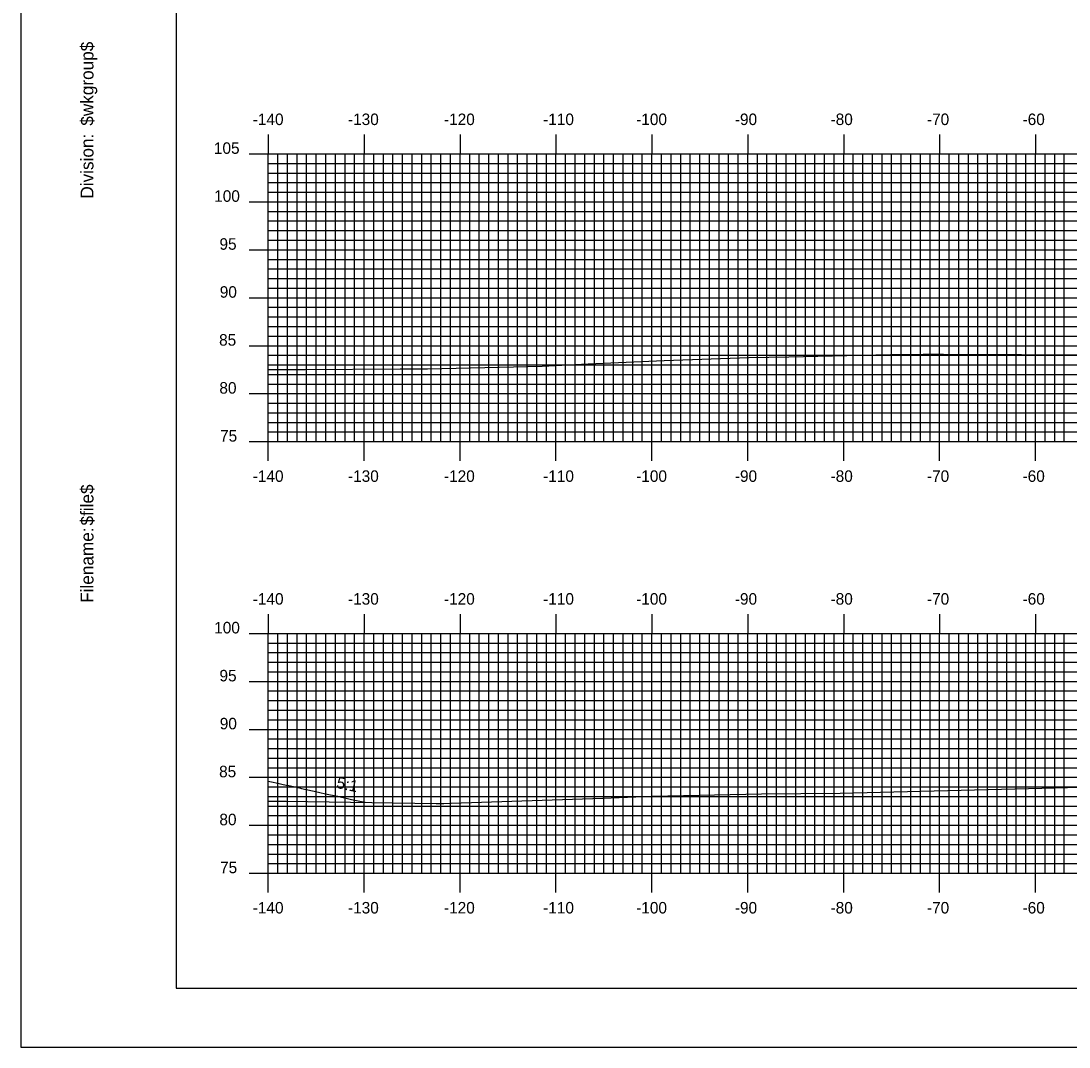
# Model space of a CAD drawing. Extents: x 2059 to 2403, y -1658 to -1438.
# Drawn here: x 2059.4 to 2168.7, y -1657.7 to -1550.7 of the extents above; entities that cross this region are included whole.
import ezdxf

# ---------------------------------------------------------------- set-up
doc = ezdxf.new("R2010")
doc.units = 0
for name, color, linetype in [('ANNOTATION', 7, 'Continuous'), ('BORDER', 7, 'Continuous'), ('D_Roadway_Centerline', 7, 'Continuous'), ('H_V ANNOTATION', 7, 'Continuous'), ('MAJOR', 7, 'Continuous'), ('MINOR', 7, 'Continuous'), ('PLOT BOUNDARY', 7, 'Continuous'), ('S_Roadway_Centerline', 7, 'Continuous')]:
    doc.layers.add(name, color=color, linetype=linetype)

msp = doc.modelspace()

# ---------------------------------------------------------------- linework, layer by layer
at = {"layer": 'BORDER'}
msp.add_lwpolyline([(2075.59, -1651.6), (2395.59, -1651.6), (2395.59, -1441.6), (2075.59, -1441.6)], close=True, dxfattribs=at)
at = {"layer": 'D_Roadway_Centerline'}
msp.add_lwpolyline([(2085.19, -1630), (2085.71, -1630.11), (2086.01, -1630.18), (2087.07, -1630.41), (2087.33, -1630.47), (2088.44, -1630.71), (2088.65, -1630.76), (2089.8, -1631.01), (2089.97, -1631.05), (2091.16, -1631.31), (2092.42, -1631.58), (2092.52, -1631.6), (2093.13, -1631.74), (2093.16, -1631.74), (2093.85, -1631.9), (2093.88, -1631.9), (2095.24, -1632.2), (2095.24, -1632.2), (2095.3, -1632.21)], dxfattribs=at)
at = {"layer": 'MAJOR'}
for p, q in [((2085.19, -1562.6), (2085.19, -1564.6)), ((2095.19, -1562.6), (2095.19, -1564.6)), ((2105.19, -1562.6), (2105.19, -1564.6)), ((2115.19, -1562.6), (2115.19, -1564.6)), ((2125.19, -1562.6), (2125.19, -1564.6)), ((2135.19, -1562.6), (2135.19, -1564.6)), ((2145.19, -1562.6), (2145.19, -1564.6)), ((2155.19, -1562.6), (2155.19, -1564.6)), ((2165.19, -1562.6), (2165.19, -1564.6)), ((2083.18, -1564.6), (2085.19, -1564.6)), ((2085.19, -1564.6), (2365.19, -1564.6)), ((2085.19, -1594.6), (2085.19, -1564.6)), ((2085.19, -1594.6), (2085.19, -1564.6)), ((2085.19, -1564.6), (2365.19, -1564.6)), ((2095.19, -1594.6), (2095.19, -1564.6)), ((2105.19, -1594.6), (2105.19, -1564.6)), ((2115.19, -1594.6), (2115.19, -1564.6)), ((2125.19, -1594.6), (2125.19, -1564.6)), ((2135.19, -1594.6), (2135.19, -1564.6)), ((2145.19, -1594.6), (2145.19, -1564.6)), ((2155.19, -1594.6), (2155.19, -1564.6)), ((2165.19, -1594.6), (2165.19, -1564.6)), ((2083.18, -1569.6), (2085.19, -1569.6)), ((2085.19, -1569.6), (2365.19, -1569.6)), ((2083.18, -1574.6), (2085.19, -1574.6)), ((2085.19, -1574.6), (2365.19, -1574.6)), ((2083.18, -1579.6), (2085.19, -1579.6)), ((2085.19, -1579.6), (2365.19, -1579.6)), ((2083.18, -1584.6), (2085.19, -1584.6)), ((2085.19, -1584.6), (2365.19, -1584.6)), ((2083.18, -1589.6), (2085.19, -1589.6)), ((2085.19, -1589.6), (2365.19, -1589.6)), ((2083.18, -1594.6), (2085.19, -1594.6)), ((2085.19, -1594.6), (2365.19, -1594.6)), ((2085.19, -1594.6), (2365.19, -1594.6)), ((2085.19, -1596.61), (2085.19, -1594.6)), ((2095.19, -1596.61), (2095.19, -1594.6)), ((2105.19, -1596.61), (2105.19, -1594.6)), ((2115.19, -1596.61), (2115.19, -1594.6)), ((2125.19, -1596.61), (2125.19, -1594.6)), ((2135.19, -1596.61), (2135.19, -1594.6)), ((2145.19, -1596.61), (2145.19, -1594.6)), ((2155.19, -1596.61), (2155.19, -1594.6)), ((2165.19, -1596.61), (2165.19, -1594.6)), ((2085.19, -1612.6), (2085.19, -1614.6)), ((2095.19, -1612.6), (2095.19, -1614.6)), ((2105.19, -1612.6), (2105.19, -1614.6)), ((2115.19, -1612.6), (2115.19, -1614.6)), ((2125.19, -1612.6), (2125.19, -1614.6)), ((2135.19, -1612.6), (2135.19, -1614.6)), ((2145.19, -1612.6), (2145.19, -1614.6)), ((2155.19, -1612.6), (2155.19, -1614.6)), ((2165.19, -1612.6), (2165.19, -1614.6)), ((2083.18, -1614.6), (2085.19, -1614.6)), ((2085.19, -1614.6), (2365.19, -1614.6)), ((2085.19, -1639.6), (2085.19, -1614.6)), ((2085.19, -1639.6), (2085.19, -1614.6)), ((2085.19, -1614.6), (2365.19, -1614.6)), ((2095.19, -1639.6), (2095.19, -1614.6)), ((2105.19, -1639.6), (2105.19, -1614.6)), ((2115.19, -1639.6), (2115.19, -1614.6)), ((2125.19, -1639.6), (2125.19, -1614.6)), ((2135.19, -1639.6), (2135.19, -1614.6)), ((2145.19, -1639.6), (2145.19, -1614.6)), ((2155.19, -1639.6), (2155.19, -1614.6)), ((2165.19, -1639.6), (2165.19, -1614.6)), ((2083.18, -1619.6), (2085.19, -1619.6)), ((2085.19, -1619.6), (2365.19, -1619.6)), ((2083.18, -1624.6), (2085.19, -1624.6)), ((2085.19, -1624.6), (2365.19, -1624.6)), ((2083.18, -1629.6), (2085.19, -1629.6)), ((2085.19, -1629.6), (2365.19, -1629.6)), ((2083.18, -1634.6), (2085.19, -1634.6)), ((2085.19, -1634.6), (2365.19, -1634.6)), ((2083.18, -1639.6), (2085.19, -1639.6)), ((2085.19, -1639.6), (2365.19, -1639.6)), ((2085.19, -1639.6), (2365.19, -1639.6)), ((2085.19, -1641.61), (2085.19, -1639.6)), ((2095.19, -1641.61), (2095.19, -1639.6)), ((2105.19, -1641.61), (2105.19, -1639.6)), ((2115.19, -1641.61), (2115.19, -1639.6)), ((2125.19, -1641.61), (2125.19, -1639.6)), ((2135.19, -1641.61), (2135.19, -1639.6)), ((2145.19, -1641.61), (2145.19, -1639.6)), ((2155.19, -1641.61), (2155.19, -1639.6)), ((2165.19, -1641.61), (2165.19, -1639.6))]:
    msp.add_line(p, q, dxfattribs=at)
at = {"layer": 'MINOR'}
for p, q in [((2086.19, -1594.6), (2086.19, -1564.6)), ((2087.19, -1594.6), (2087.19, -1564.6)), ((2088.19, -1594.6), (2088.19, -1564.6)), ((2089.19, -1594.6), (2089.19, -1564.6)), ((2090.19, -1594.6), (2090.19, -1564.6)), ((2091.19, -1594.6), (2091.19, -1564.6)), ((2092.19, -1594.6), (2092.19, -1564.6)), ((2093.19, -1594.6), (2093.19, -1564.6)), ((2094.19, -1594.6), (2094.19, -1564.6)), ((2096.19, -1594.6), (2096.19, -1564.6)), ((2097.19, -1594.6), (2097.19, -1564.6)), ((2098.19, -1594.6), (2098.19, -1564.6)), ((2099.19, -1594.6), (2099.19, -1564.6)), ((2100.19, -1594.6), (2100.19, -1564.6)), ((2101.19, -1594.6), (2101.19, -1564.6)), ((2102.19, -1594.6), (2102.19, -1564.6)), ((2103.19, -1594.6), (2103.19, -1564.6)), ((2104.19, -1594.6), (2104.19, -1564.6)), ((2106.19, -1594.6), (2106.19, -1564.6)), ((2107.19, -1594.6), (2107.19, -1564.6)), ((2108.19, -1594.6), (2108.19, -1564.6)), ((2109.19, -1594.6), (2109.19, -1564.6)), ((2110.19, -1594.6), (2110.19, -1564.6)), ((2111.19, -1594.6), (2111.19, -1564.6)), ((2112.19, -1594.6), (2112.19, -1564.6)), ((2113.19, -1594.6), (2113.19, -1564.6)), ((2114.19, -1594.6), (2114.19, -1564.6)), ((2116.19, -1594.6), (2116.19, -1564.6)), ((2117.19, -1594.6), (2117.19, -1564.6)), ((2118.19, -1594.6), (2118.19, -1564.6)), ((2119.19, -1594.6), (2119.19, -1564.6)), ((2120.19, -1594.6), (2120.19, -1564.6)), ((2121.19, -1594.6), (2121.19, -1564.6)), ((2122.19, -1594.6), (2122.19, -1564.6)), ((2123.19, -1594.6), (2123.19, -1564.6)), ((2124.19, -1594.6), (2124.19, -1564.6)), ((2126.19, -1594.6), (2126.19, -1564.6)), ((2127.19, -1594.6), (2127.19, -1564.6)), ((2128.19, -1594.6), (2128.19, -1564.6)), ((2129.19, -1594.6), (2129.19, -1564.6)), ((2130.19, -1594.6), (2130.19, -1564.6)), ((2131.19, -1594.6), (2131.19, -1564.6)), ((2132.19, -1594.6), (2132.19, -1564.6)), ((2133.19, -1594.6), (2133.19, -1564.6)), ((2134.19, -1594.6), (2134.19, -1564.6)), ((2136.19, -1594.6), (2136.19, -1564.6)), ((2137.19, -1594.6), (2137.19, -1564.6)), ((2138.19, -1594.6), (2138.19, -1564.6)), ((2139.19, -1594.6), (2139.19, -1564.6)), ((2140.19, -1594.6), (2140.19, -1564.6)), ((2141.19, -1594.6), (2141.19, -1564.6)), ((2142.19, -1594.6), (2142.19, -1564.6)), ((2143.19, -1594.6), (2143.19, -1564.6)), ((2144.19, -1594.6), (2144.19, -1564.6)), ((2146.19, -1594.6), (2146.19, -1564.6)), ((2147.19, -1594.6), (2147.19, -1564.6)), ((2148.19, -1594.6), (2148.19, -1564.6)), ((2149.19, -1594.6), (2149.19, -1564.6)), ((2150.19, -1594.6), (2150.19, -1564.6)), ((2151.19, -1594.6), (2151.19, -1564.6)), ((2152.19, -1594.6), (2152.19, -1564.6)), ((2153.19, -1594.6), (2153.19, -1564.6)), ((2154.19, -1594.6), (2154.19, -1564.6)), ((2156.19, -1594.6), (2156.19, -1564.6)), ((2157.19, -1594.6), (2157.19, -1564.6)), ((2158.19, -1594.6), (2158.19, -1564.6)), ((2159.19, -1594.6), (2159.19, -1564.6)), ((2160.19, -1594.6), (2160.19, -1564.6)), ((2161.19, -1594.6), (2161.19, -1564.6)), ((2162.19, -1594.6), (2162.19, -1564.6)), ((2163.19, -1594.6), (2163.19, -1564.6)), ((2164.19, -1594.6), (2164.19, -1564.6)), ((2166.19, -1594.6), (2166.19, -1564.6)), ((2167.19, -1594.6), (2167.19, -1564.6)), ((2168.19, -1594.6), (2168.19, -1564.6)), ((2085.19, -1565.6), (2365.19, -1565.6)), ((2085.19, -1565.6), (2087.19, -1565.6)), ((2085.19, -1566.6), (2365.19, -1566.6)), ((2085.19, -1566.6), (2087.19, -1566.6)), ((2085.19, -1567.6), (2365.19, -1567.6)), ((2085.19, -1567.6), (2087.19, -1567.6)), ((2085.19, -1568.6), (2365.19, -1568.6)), ((2085.19, -1568.6), (2087.19, -1568.6)), ((2085.19, -1570.6), (2365.19, -1570.6)), ((2085.19, -1570.6), (2087.19, -1570.6)), ((2085.19, -1571.6), (2365.19, -1571.6)), ((2085.19, -1571.6), (2087.19, -1571.6)), ((2085.19, -1572.6), (2365.19, -1572.6)), ((2085.19, -1572.6), (2087.19, -1572.6)), ((2085.19, -1573.6), (2365.19, -1573.6)), ((2085.19, -1573.6), (2087.19, -1573.6)), ((2085.19, -1575.6), (2365.19, -1575.6)), ((2085.19, -1575.6), (2087.19, -1575.6)), ((2085.19, -1576.6), (2365.19, -1576.6)), ((2085.19, -1576.6), (2087.19, -1576.6)), ((2085.19, -1577.6), (2365.19, -1577.6)), ((2085.19, -1577.6), (2087.19, -1577.6)), ((2085.19, -1578.6), (2365.19, -1578.6)), ((2085.19, -1578.6), (2087.19, -1578.6)), ((2085.19, -1580.6), (2365.19, -1580.6)), ((2085.19, -1580.6), (2087.19, -1580.6)), ((2085.19, -1581.6), (2365.19, -1581.6)), ((2085.19, -1581.6), (2087.19, -1581.6)), ((2085.19, -1582.6), (2365.19, -1582.6)), ((2085.19, -1582.6), (2087.19, -1582.6)), ((2085.19, -1583.6), (2365.19, -1583.6)), ((2085.19, -1583.6), (2087.19, -1583.6)), ((2085.19, -1585.6), (2365.19, -1585.6)), ((2085.19, -1585.6), (2087.19, -1585.6)), ((2085.19, -1586.6), (2365.19, -1586.6)), ((2085.19, -1586.6), (2087.19, -1586.6)), ((2085.19, -1587.6), (2365.19, -1587.6)), ((2085.19, -1587.6), (2087.19, -1587.6)), ((2085.19, -1588.6), (2365.19, -1588.6)), ((2085.19, -1588.6), (2087.19, -1588.6)), ((2085.19, -1590.6), (2365.19, -1590.6)), ((2085.19, -1590.6), (2087.19, -1590.6)), ((2085.19, -1591.6), (2365.19, -1591.6)), ((2085.19, -1591.6), (2087.19, -1591.6)), ((2085.19, -1592.6), (2365.19, -1592.6)), ((2085.19, -1592.6), (2087.19, -1592.6)), ((2085.19, -1593.6), (2365.19, -1593.6)), ((2085.19, -1593.6), (2087.19, -1593.6)), ((2086.19, -1639.6), (2086.19, -1614.6)), ((2087.19, -1639.6), (2087.19, -1614.6)), ((2088.19, -1639.6), (2088.19, -1614.6)), ((2089.19, -1639.6), (2089.19, -1614.6)), ((2090.19, -1639.6), (2090.19, -1614.6)), ((2091.19, -1639.6), (2091.19, -1614.6)), ((2092.19, -1639.6), (2092.19, -1614.6)), ((2093.19, -1639.6), (2093.19, -1614.6)), ((2094.19, -1639.6), (2094.19, -1614.6)), ((2096.19, -1639.6), (2096.19, -1614.6)), ((2097.19, -1639.6), (2097.19, -1614.6)), ((2098.19, -1639.6), (2098.19, -1614.6)), ((2099.19, -1639.6), (2099.19, -1614.6)), ((2100.19, -1639.6), (2100.19, -1614.6)), ((2101.19, -1639.6), (2101.19, -1614.6)), ((2102.19, -1639.6), (2102.19, -1614.6)), ((2103.19, -1639.6), (2103.19, -1614.6)), ((2104.19, -1639.6), (2104.19, -1614.6)), ((2106.19, -1639.6), (2106.19, -1614.6)), ((2107.19, -1639.6), (2107.19, -1614.6)), ((2108.19, -1639.6), (2108.19, -1614.6)), ((2109.19, -1639.6), (2109.19, -1614.6)), ((2110.19, -1639.6), (2110.19, -1614.6)), ((2111.19, -1639.6), (2111.19, -1614.6)), ((2112.19, -1639.6), (2112.19, -1614.6)), ((2113.19, -1639.6), (2113.19, -1614.6)), ((2114.19, -1639.6), (2114.19, -1614.6)), ((2116.19, -1639.6), (2116.19, -1614.6)), ((2117.19, -1639.6), (2117.19, -1614.6)), ((2118.19, -1639.6), (2118.19, -1614.6)), ((2119.19, -1639.6), (2119.19, -1614.6)), ((2120.19, -1639.6), (2120.19, -1614.6)), ((2121.19, -1639.6), (2121.19, -1614.6)), ((2122.19, -1639.6), (2122.19, -1614.6)), ((2123.19, -1639.6), (2123.19, -1614.6)), ((2124.19, -1639.6), (2124.19, -1614.6)), ((2126.19, -1639.6), (2126.19, -1614.6)), ((2127.19, -1639.6), (2127.19, -1614.6)), ((2128.19, -1639.6), (2128.19, -1614.6)), ((2129.19, -1639.6), (2129.19, -1614.6)), ((2130.19, -1639.6), (2130.19, -1614.6)), ((2131.19, -1639.6), (2131.19, -1614.6)), ((2132.19, -1639.6), (2132.19, -1614.6)), ((2133.19, -1639.6), (2133.19, -1614.6)), ((2134.19, -1639.6), (2134.19, -1614.6)), ((2136.19, -1639.6), (2136.19, -1614.6)), ((2137.19, -1639.6), (2137.19, -1614.6)), ((2138.19, -1639.6), (2138.19, -1614.6)), ((2139.19, -1639.6), (2139.19, -1614.6)), ((2140.19, -1639.6), (2140.19, -1614.6)), ((2141.19, -1639.6), (2141.19, -1614.6)), ((2142.19, -1639.6), (2142.19, -1614.6)), ((2143.19, -1639.6), (2143.19, -1614.6)), ((2144.19, -1639.6), (2144.19, -1614.6)), ((2146.19, -1639.6), (2146.19, -1614.6)), ((2147.19, -1639.6), (2147.19, -1614.6)), ((2148.19, -1639.6), (2148.19, -1614.6)), ((2149.19, -1639.6), (2149.19, -1614.6)), ((2150.19, -1639.6), (2150.19, -1614.6)), ((2151.19, -1639.6), (2151.19, -1614.6)), ((2152.19, -1639.6), (2152.19, -1614.6)), ((2153.19, -1639.6), (2153.19, -1614.6)), ((2154.19, -1639.6), (2154.19, -1614.6)), ((2156.19, -1639.6), (2156.19, -1614.6)), ((2157.19, -1639.6), (2157.19, -1614.6)), ((2158.19, -1639.6), (2158.19, -1614.6)), ((2159.19, -1639.6), (2159.19, -1614.6)), ((2160.19, -1639.6), (2160.19, -1614.6)), ((2161.19, -1639.6), (2161.19, -1614.6)), ((2162.19, -1639.6), (2162.19, -1614.6)), ((2163.19, -1639.6), (2163.19, -1614.6)), ((2164.19, -1639.6), (2164.19, -1614.6)), ((2166.19, -1639.6), (2166.19, -1614.6)), ((2167.19, -1639.6), (2167.19, -1614.6)), ((2168.19, -1639.6), (2168.19, -1614.6)), ((2085.19, -1615.6), (2365.19, -1615.6)), ((2085.19, -1615.6), (2087.19, -1615.6)), ((2085.19, -1616.6), (2365.19, -1616.6)), ((2085.19, -1616.6), (2087.19, -1616.6)), ((2085.19, -1617.6), (2365.19, -1617.6)), ((2085.19, -1617.6), (2087.19, -1617.6)), ((2085.19, -1618.6), (2365.19, -1618.6)), ((2085.19, -1618.6), (2087.19, -1618.6)), ((2085.19, -1620.6), (2365.19, -1620.6)), ((2085.19, -1620.6), (2087.19, -1620.6)), ((2085.19, -1621.6), (2365.19, -1621.6)), ((2085.19, -1621.6), (2087.19, -1621.6)), ((2085.19, -1622.6), (2365.19, -1622.6)), ((2085.19, -1622.6), (2087.19, -1622.6)), ((2085.19, -1623.6), (2365.19, -1623.6)), ((2085.19, -1623.6), (2087.19, -1623.6)), ((2085.19, -1625.6), (2365.19, -1625.6)), ((2085.19, -1625.6), (2087.19, -1625.6)), ((2085.19, -1626.6), (2365.19, -1626.6)), ((2085.19, -1626.6), (2087.19, -1626.6)), ((2085.19, -1627.6), (2365.19, -1627.6)), ((2085.19, -1627.6), (2087.19, -1627.6)), ((2085.19, -1628.6), (2365.19, -1628.6)), ((2085.19, -1628.6), (2087.19, -1628.6)), ((2085.19, -1630.6), (2365.19, -1630.6)), ((2085.19, -1630.6), (2087.19, -1630.6)), ((2085.19, -1631.6), (2365.19, -1631.6)), ((2085.19, -1631.6), (2087.19, -1631.6)), ((2085.19, -1632.6), (2365.19, -1632.6)), ((2085.19, -1632.6), (2087.19, -1632.6)), ((2085.19, -1633.6), (2365.19, -1633.6)), ((2085.19, -1633.6), (2087.19, -1633.6)), ((2085.19, -1635.6), (2365.19, -1635.6)), ((2085.19, -1635.6), (2087.19, -1635.6)), ((2085.19, -1636.6), (2365.19, -1636.6)), ((2085.19, -1636.6), (2087.19, -1636.6)), ((2085.19, -1637.6), (2365.19, -1637.6)), ((2085.19, -1637.6), (2087.19, -1637.6)), ((2085.19, -1638.6), (2365.19, -1638.6)), ((2085.19, -1638.6), (2087.19, -1638.6))]:
    msp.add_line(p, q, dxfattribs=at)
at = {"layer": 'PLOT BOUNDARY'}
msp.add_lwpolyline([(2059.4, -1657.72), (2399.4, -1657.72), (2399.4, -1437.72), (2059.4, -1437.72)], close=True, dxfattribs=at)
at = {"layer": 'S_Roadway_Centerline'}
for points in [[(2085.19, -1587.08), (2089.02, -1587.07), (2098.93, -1587.02), (2101.78, -1587.02), (2113.75, -1586.74), (2118.53, -1586.48), (2126.48, -1586.13), (2135.29, -1585.85), (2139.47, -1585.78), (2150.07, -1585.52), (2153.48, -1585.5), (2155.58, -1585.48), (2171.86, -1585.54)], [(2085.19, -1632.08), (2087.05, -1632.09), (2102.69, -1632.32), (2103.24, -1632.34), (2103.49, -1632.33), (2104.26, -1632.3), (2120.09, -1631.76), (2125.23, -1631.56), (2136.61, -1631.32), (2144.83, -1631.26), (2165.86, -1630.74), (2169.87, -1630.62)]]:
    msp.add_lwpolyline(points, dxfattribs=at)

# ---------------------------------------------------------------- texts
at = {"layer": 'ANNOTATION'}
msp.add_text('5:1', height=1.2, rotation=347.6601, dxfattribs=at).set_placement((2092.22, -1630.69))
at = {"layer": 'BORDER'}
for s, p in [('$wkgroup$', (2066.96, -1561.67)), ('Division:', (2066.96, -1569.27)), ('$file$', (2066.96, -1603.35)), ('Filename:', (2066.96, -1611.41))]:
    msp.add_text(s, height=1.339, rotation=90, dxfattribs=at).set_placement(p)
at = {"layer": 'H_V ANNOTATION'}
for s, p in [('-140', (2083.57, -1561.6)), ('-130', (2093.5, -1561.6)), ('-120', (2103.51, -1561.6)), ('-110', (2113.85, -1561.6)), ('-100', (2123.55, -1561.6)), ('-90', (2133.84, -1561.6)), ('-80', (2143.82, -1561.6)), ('-70', (2153.87, -1561.6)), ('-60', (2163.84, -1561.6)), ('105', (2079.52, -1564.6)), ('100', (2079.55, -1569.6)), ('95', (2080.1, -1574.6)), ('90', (2080.13, -1579.6)), ('85', (2080.06, -1584.6)), ('80', (2080.09, -1589.6)), ('75', (2080.16, -1594.6)), ('-140', (2083.57, -1598.8)), ('-130', (2093.5, -1598.8)), ('-120', (2103.51, -1598.8)), ('-110', (2113.85, -1598.8)), ('-100', (2123.55, -1598.8)), ('-90', (2133.84, -1598.8)), ('-80', (2143.82, -1598.8)), ('-70', (2153.87, -1598.8)), ('-60', (2163.84, -1598.8)), ('-140', (2083.57, -1611.6)), ('-130', (2093.5, -1611.6)), ('-120', (2103.51, -1611.6)), ('-110', (2113.85, -1611.6)), ('-100', (2123.55, -1611.6)), ('-90', (2133.84, -1611.6)), ('-80', (2143.82, -1611.6)), ('-70', (2153.87, -1611.6)), ('-60', (2163.84, -1611.6)), ('100', (2079.55, -1614.6)), ('95', (2080.1, -1619.6)), ('90', (2080.13, -1624.6)), ('85', (2080.06, -1629.6)), ('80', (2080.09, -1634.6)), ('75', (2080.16, -1639.6)), ('-140', (2083.57, -1643.8)), ('-130', (2093.5, -1643.8)), ('-120', (2103.51, -1643.8)), ('-110', (2113.85, -1643.8)), ('-100', (2123.55, -1643.8)), ('-90', (2133.84, -1643.8)), ('-80', (2143.82, -1643.8)), ('-70', (2153.87, -1643.8)), ('-60', (2163.84, -1643.8))]:
    msp.add_text(s, height=1.2, dxfattribs=at).set_placement(p)
at = {"layer": 'MAJOR'}
for p in [(2085.18, -1594.6), (2085.18, -1639.6)]:
    msp.add_text('-', height=0.012, dxfattribs=at).set_placement(p)

doc.saveas('drawing.dxf')
